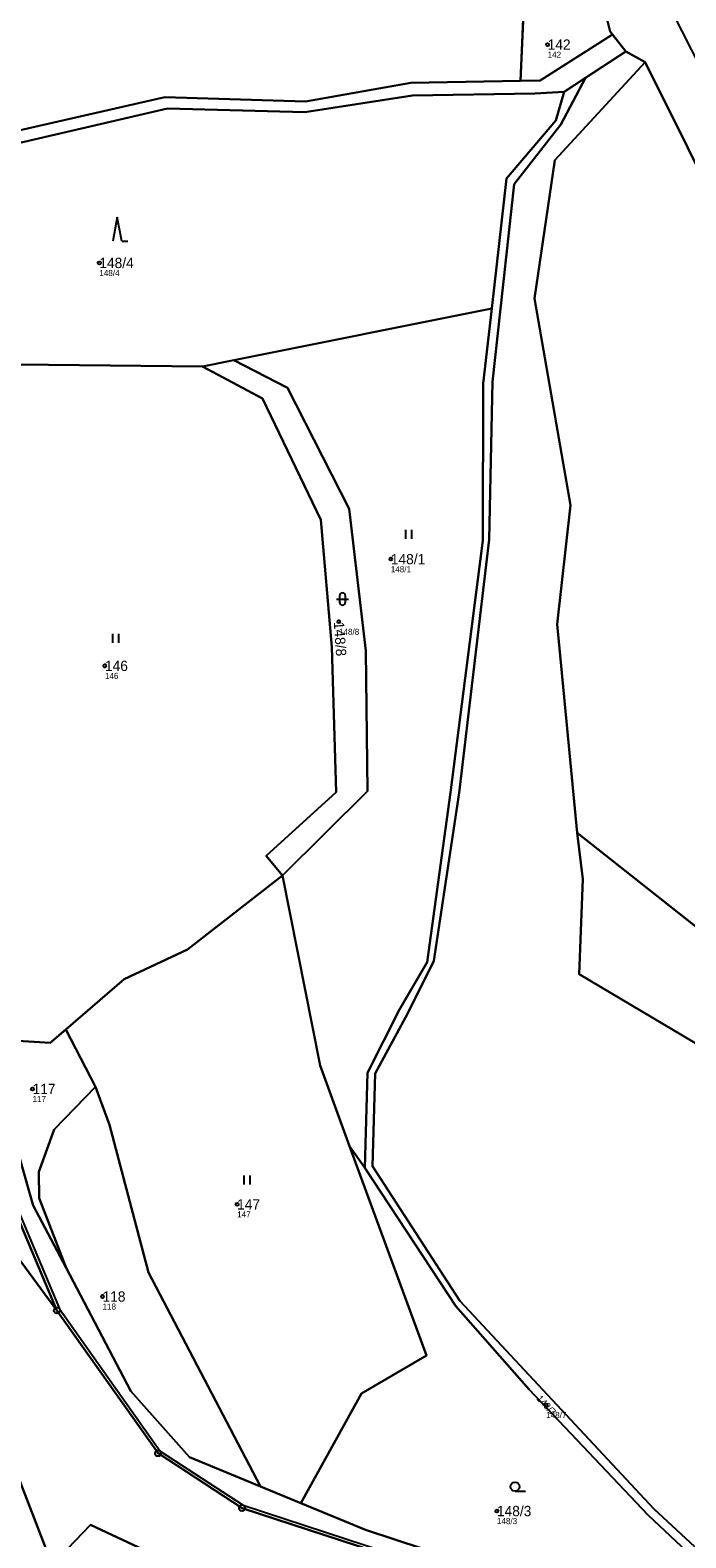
# Model space of a CAD drawing. Extents: x -770088 to -765625, y -1057899 to -1053934.
# Drawn here: x -768095.1 to -767987, y -1054686.7 to -1054438.1 of the extents above; entities that cross this region are included whole.
import ezdxf

# ---------------------------------------------------------------- set-up
doc = ezdxf.new("R2010")
doc.units = 0
for name, color, linetype in [('Definiční body', 7, 'Continuous'), ('Hranice parcel', 7, 'Continuous'), ('Parcelní čísla', 7, 'Continuous'), ('Polygon parcely', 7, 'Continuous'), ('Poz předměty', 7, 'Continuous'), ('Vnitřní kresba', 7, 'Continuous'), ('Značky bodu BP', 7, 'Continuous'), ('Značky kultur', 7, 'Continuous')]:
    doc.layers.add(name, color=color, linetype=linetype)

msp = doc.modelspace()

# ---------------------------------------------------------------- linework, layer by layer
at = {"layer": 'Definiční body'}
for centre in [(-768009.84, -1054440.53), (-768083.75, -1054476.52), (-768035.69, -1054525.35), (-768044.24, -1054535.67), (-768082.82, -1054542.94), (-768094.76, -1054612.7), (-768061.03, -1054631.72), (-768083.22, -1054646.91), (-768010.07, -1054664.79), (-768018.2, -1054682.28)]:
    msp.add_circle(centre, 0.25, dxfattribs=at)
at = {"layer": 'Hranice parcel'}
for p, q in [((-768014.32, -1054446.48), (-768012.63, -1054409.53)), ((-768011.07, -1054446.42), (-767999.13, -1054438.86)), ((-767996.92, -1054441.64), (-767999.13, -1054438.86)), ((-767996.92, -1054441.64), (-768003.58, -1054446.01)), ((-767993.75, -1054443.41), (-767996.92, -1054441.64)), ((-768003.58, -1054446.01), (-768007.65, -1054453.72)), ((-768003.58, -1054446.01), (-768007.12, -1054448.33)), ((-768014.32, -1054446.48), (-768011.07, -1054446.42)), ((-768019.05, -1054484.05), (-768016.59, -1054462.59)), ((-768019.05, -1054484.05), (-768061.59, -1054492.55)), ((-768020.47, -1054496.39), (-768019.05, -1054484.05)), ((-768066.71, -1054493.58), (-768061.59, -1054492.55)), ((-768004.98, -1054570.49), (-767952.69, -1054611.77)), ((-768089.29, -1054602.92), (-768084.35, -1054612.32)), ((-768042.48, -1054622.1), (-768039.98, -1054625.68)), ((-768068.87, -1054673.41), (-768057.15, -1054678.25)), ((-768057.15, -1054678.25), (-768050.53, -1054680.98)), ((-768050.53, -1054680.98), (-768039.86, -1054685.38))]:
    msp.add_line(p, q, dxfattribs=at)
for points in [[(-767999.13, -1054438.86), (-767999.51, -1054438.37), (-768000.9, -1054433), (-768001.9, -1054430.25)], [(-768004.98, -1054570.49), (-768008.26, -1054536.06), (-768006.08, -1054516.43), (-768011.97, -1054482.37), (-768008.62, -1054459.57), (-767993.75, -1054443.41)], [(-767932.49, -1054594.98), (-767947.43, -1054549.64), (-767965.69, -1054499.79), (-767993.75, -1054443.41)], [(-768129.66, -1054522.44), (-768143.72, -1054508.36), (-768153.51, -1054496.13), (-768145.69, -1054479.12), (-768128.76, -1054467.46), (-768108.88, -1054457.38), (-768072.94, -1054449.18), (-768049.77, -1054449.9), (-768032.41, -1054446.8), (-768014.32, -1054446.48)], [(-768007.12, -1054448.33), (-768011.94, -1054448.56), (-768032.09, -1054448.91), (-768049.87, -1054451.68), (-768072.5, -1054451.08), (-768107.99, -1054459.29), (-768127.24, -1054469.4), (-768144.62, -1054481.32), (-768150.8, -1054495.47), (-768142.12, -1054506.4), (-768138.56, -1054510)], [(-768016.59, -1054462.59), (-768008.46, -1054453.04), (-768007.12, -1054448.33)], [(-768007.65, -1054453.72), (-768015.36, -1054463.55), (-768018.91, -1054496.12), (-768019.46, -1054522.13), (-768024.43, -1054563.88), (-768028.6, -1054591.56), (-768032.87, -1054600.19), (-768038.24, -1054610.16), (-768038.7, -1054625.42), (-768024.3, -1054647.61), (-767992.32, -1054681.94), (-767984.09, -1054689.56)], [(-768066.71, -1054493.58), (-768097.17, -1054493.26), (-768124.91, -1054502.9)], [(-768061.59, -1054492.55), (-768052.73, -1054497.13), (-768042.56, -1054517.08), (-768039.81, -1054540.47), (-768039.55, -1054563.6), (-768053.52, -1054577.48)], [(-768053.52, -1054577.48), (-768056.26, -1054574.26), (-768044.72, -1054563.77), (-768045.4, -1054539.87), (-768047.21, -1054518.89), (-768056.86, -1054498.85), (-768066.71, -1054493.58)], [(-768039.98, -1054625.68), (-768039.52, -1054610.02), (-768034.26, -1054599.61), (-768029.7, -1054591.8), (-768025.82, -1054563.82), (-768020.53, -1054522.28), (-768020.47, -1054496.39)], [(-767952.69, -1054611.77), (-767961.76, -1054619.22), (-768004.62, -1054593.77), (-768004.01, -1054578.13), (-768004.98, -1054570.49)], [(-768089.29, -1054602.92), (-768079.66, -1054594.62), (-768069.23, -1054589.69), (-768053.52, -1054577.48)], [(-768042.48, -1054622.1), (-768047.34, -1054608.85), (-768053.52, -1054577.48)], [(-768103.45, -1054604.38), (-768091.83, -1054605.1), (-768089.29, -1054602.92)], [(-768090.72, -1054649.21), (-768097.97, -1054632.05), (-768103.4, -1054615), (-768106.26, -1054607.33)], [(-768084.35, -1054612.32), (-768091.18, -1054619.39), (-768093.74, -1054626.36), (-768093.67, -1054630.71), (-768089.23, -1054642.19)], [(-768057.15, -1054678.25), (-768075.64, -1054642.95), (-768082.06, -1054618.63), (-768084.35, -1054612.32)], [(-768089.23, -1054642.19), (-768094.64, -1054631.93), (-768098.83, -1054617.23)], [(-768114.36, -1054622.39), (-768110.66, -1054620.35), (-768106.49, -1054627.9), (-768090.72, -1054649.21)], [(-768091.51, -1054691.14), (-768104.48, -1054657.68), (-768112.02, -1054633.85), (-768114.36, -1054622.39)], [(-768050.53, -1054680.98), (-768040.54, -1054662.9), (-768029.82, -1054656.63), (-768042.48, -1054622.1)], [(-767931.74, -1054768.14), (-767931.44, -1054758.8), (-767936.62, -1054749.49), (-767951.16, -1054722.75), (-767974.99, -1054700.13), (-767993.27, -1054682.98), (-768012.87, -1054662.27), (-768024.96, -1054648.49), (-768039.98, -1054625.68)], [(-768089.23, -1054642.19), (-768078.52, -1054662.51), (-768068.87, -1054673.41)], [(-767968, -1054727.23), (-768001.95, -1054702.62), (-768016.95, -1054695.94), (-768060.2, -1054681.78), (-768074.06, -1054672.76), (-768090.72, -1054649.21)], [(-768091.51, -1054691.14), (-768085.17, -1054684.55), (-768066.76, -1054693.17), (-768053.98, -1054697.96), (-768050.09, -1054703.07), (-768035.06, -1054714.6), (-768021.61, -1054726.81), (-768017.92, -1054728.84), (-768013.91, -1054731.45), (-767995.48, -1054757.12)], [(-768039.86, -1054685.38), (-768011.31, -1054694.75), (-768001.18, -1054699.79), (-767994.33, -1054704.31), (-767972.32, -1054720.42), (-767961.3, -1054728.83), (-767941.91, -1054747.99), (-767934.66, -1054760.27), (-767931.74, -1054768.14)]]:
    msp.add_lwpolyline(points, dxfattribs=at)
at = {"layer": 'Polygon parcely'}
for points in [[(-768108.88, -1054457.38), (-768072.94, -1054449.18), (-768049.77, -1054449.9), (-768032.41, -1054446.8), (-768014.32, -1054446.48), (-768012.63, -1054409.53)], [(-768000.9, -1054433), (-767999.51, -1054438.37), (-767999.13, -1054438.86), (-767996.92, -1054441.64), (-767993.75, -1054443.41), (-767965.69, -1054499.79), (-767947.43, -1054549.64), (-767932.49, -1054594.98), (-767914.06, -1054628.49), (-767911.41, -1054626.68), (-767903.01, -1054638.57), (-767897.05, -1054647), (-767882.98, -1054666.9), (-767874.18, -1054679.35), (-767864.97, -1054691.97), (-767847.09, -1054711.31), (-767838.93, -1054720.15), (-767832.46, -1054727.15), (-767814.04, -1054742.81), (-767801.61, -1054749.28), (-767725.45, -1054824.62), (-767692.81, -1054850)], [(-768107.99, -1054459.29), (-768072.5, -1054451.08), (-768049.87, -1054451.68), (-768032.09, -1054448.91), (-768011.94, -1054448.56), (-768007.12, -1054448.33), (-768003.58, -1054446.01), (-767996.92, -1054441.64), (-767999.13, -1054438.86), (-768011.07, -1054446.42), (-768014.32, -1054446.48), (-768032.41, -1054446.8), (-768049.77, -1054449.9), (-768072.94, -1054449.18), (-768108.88, -1054457.38)], [(-767961.76, -1054619.22), (-768004.62, -1054593.77), (-768004.01, -1054578.13), (-768004.98, -1054570.49), (-768008.26, -1054536.06), (-768006.08, -1054516.43), (-768011.97, -1054482.37), (-768008.62, -1054459.57), (-767993.75, -1054443.41), (-767996.92, -1054441.64), (-768003.58, -1054446.01), (-768007.65, -1054453.72), (-768015.36, -1054463.55), (-768018.91, -1054496.12), (-768019.46, -1054522.13), (-768024.43, -1054563.88), (-768028.6, -1054591.56), (-768032.87, -1054600.19), (-768038.24, -1054610.16), (-768038.7, -1054625.42), (-768024.3, -1054647.61), (-767992.32, -1054681.94), (-767984.09, -1054689.56)], [(-767984.09, -1054689.56), (-767992.32, -1054681.94), (-768024.3, -1054647.61), (-768038.7, -1054625.42), (-768038.24, -1054610.16), (-768032.87, -1054600.19), (-768028.6, -1054591.56), (-768024.43, -1054563.88), (-768019.46, -1054522.13), (-768018.91, -1054496.12), (-768015.36, -1054463.55), (-768007.65, -1054453.72), (-768003.58, -1054446.01), (-768007.12, -1054448.33), (-768008.46, -1054453.04), (-768016.59, -1054462.59), (-768019.05, -1054484.05), (-768020.47, -1054496.39), (-768020.53, -1054522.28), (-768025.82, -1054563.82), (-768029.7, -1054591.8), (-768034.26, -1054599.61), (-768039.52, -1054610.02), (-768039.98, -1054625.68), (-768024.96, -1054648.49), (-768012.87, -1054662.27), (-767993.27, -1054682.98), (-767974.99, -1054700.13)], [(-768011.31, -1054694.75), (-768039.86, -1054685.38), (-768050.53, -1054680.98), (-768057.15, -1054678.25), (-768068.87, -1054673.41), (-768078.52, -1054662.51), (-768089.23, -1054642.19), (-768094.64, -1054631.93), (-768098.83, -1054617.23)], [(-768097.97, -1054632.05), (-768090.72, -1054649.21), (-768074.06, -1054672.76), (-768060.2, -1054681.78), (-768016.95, -1054695.94)]]:
    msp.add_lwpolyline(points, dxfattribs=at)
for points in [[(-768011.07, -1054446.42), (-767999.13, -1054438.86), (-767999.51, -1054438.37), (-768000.9, -1054433), (-768001.9, -1054430.25), (-768008.13, -1054434.58), (-768010.27, -1054412.89), (-768012.63, -1054409.53), (-768014.32, -1054446.48)], [(-767993.75, -1054443.41), (-768008.62, -1054459.57), (-768011.97, -1054482.37), (-768006.08, -1054516.43), (-768008.26, -1054536.06), (-768004.98, -1054570.49), (-767952.69, -1054611.77), (-767946.58, -1054606.74), (-767932.49, -1054594.98), (-767947.43, -1054549.64), (-767965.69, -1054499.79)], [(-768019.05, -1054484.05), (-768016.59, -1054462.59), (-768008.46, -1054453.04), (-768007.12, -1054448.33), (-768011.94, -1054448.56), (-768032.09, -1054448.91), (-768049.87, -1054451.68), (-768072.5, -1054451.08), (-768107.99, -1054459.29), (-768127.24, -1054469.4), (-768144.62, -1054481.32), (-768150.8, -1054495.47), (-768142.12, -1054506.4), (-768138.56, -1054510), (-768124.91, -1054502.9), (-768097.17, -1054493.26), (-768066.71, -1054493.58), (-768061.59, -1054492.55)], [(-768025.82, -1054563.82), (-768020.53, -1054522.28), (-768020.47, -1054496.39), (-768019.05, -1054484.05), (-768061.59, -1054492.55), (-768052.73, -1054497.13), (-768042.56, -1054517.08), (-768039.81, -1054540.47), (-768039.55, -1054563.6), (-768053.52, -1054577.48), (-768047.34, -1054608.85), (-768042.48, -1054622.1), (-768039.98, -1054625.68), (-768039.52, -1054610.02), (-768034.26, -1054599.61), (-768029.7, -1054591.8)], [(-768069.23, -1054589.69), (-768053.52, -1054577.48), (-768056.26, -1054574.26), (-768044.72, -1054563.77), (-768045.4, -1054539.87), (-768047.21, -1054518.89), (-768056.86, -1054498.85), (-768066.71, -1054493.58), (-768097.17, -1054493.26), (-768124.91, -1054502.9), (-768115.73, -1054532.85), (-768105.46, -1054598.9), (-768103.45, -1054604.38), (-768091.83, -1054605.1), (-768089.29, -1054602.92), (-768079.66, -1054594.62)], [(-768053.52, -1054577.48), (-768039.55, -1054563.6), (-768039.81, -1054540.47), (-768042.56, -1054517.08), (-768052.73, -1054497.13), (-768061.59, -1054492.55), (-768066.71, -1054493.58), (-768056.86, -1054498.85), (-768047.21, -1054518.89), (-768045.4, -1054539.87), (-768044.72, -1054563.77), (-768056.26, -1054574.26)], [(-767952.69, -1054611.77), (-768004.98, -1054570.49), (-768004.01, -1054578.13), (-768004.62, -1054593.77), (-767961.76, -1054619.22)], [(-768089.29, -1054602.92), (-768084.35, -1054612.32), (-768082.06, -1054618.63), (-768075.64, -1054642.95), (-768057.15, -1054678.25), (-768050.53, -1054680.98), (-768040.54, -1054662.9), (-768029.82, -1054656.63), (-768042.48, -1054622.1), (-768047.34, -1054608.85), (-768053.52, -1054577.48), (-768069.23, -1054589.69), (-768079.66, -1054594.62)], [(-768107.8, -1054607.68), (-768117.43, -1054591.21), (-768124.72, -1054593.33), (-768123.55, -1054596.45), (-768114.36, -1054622.39), (-768110.66, -1054620.35), (-768106.49, -1054627.9), (-768090.72, -1054649.21), (-768097.97, -1054632.05), (-768103.4, -1054615), (-768106.26, -1054607.33)], [(-768135.13, -1054684.39), (-768135.76, -1054687.61), (-768131.99, -1054691.07), (-768121.57, -1054697.67), (-768094.16, -1054712.91), (-768059.31, -1054736.14), (-768073.76, -1054717.03), (-768091.51, -1054691.14), (-768104.48, -1054657.68), (-768112.02, -1054633.85), (-768114.36, -1054622.39), (-768123.55, -1054596.45), (-768124.72, -1054593.33), (-768164.23, -1054611.92), (-768142.11, -1054670.64)], [(-768089.23, -1054642.19), (-768093.67, -1054630.71), (-768093.74, -1054626.36), (-768091.18, -1054619.39), (-768084.35, -1054612.32), (-768089.29, -1054602.92), (-768091.83, -1054605.1), (-768103.45, -1054604.38), (-768098.83, -1054617.23), (-768094.64, -1054631.93)], [(-768082.06, -1054618.63), (-768084.35, -1054612.32), (-768091.18, -1054619.39), (-768093.74, -1054626.36), (-768093.67, -1054630.71), (-768089.23, -1054642.19), (-768078.52, -1054662.51), (-768068.87, -1054673.41), (-768057.15, -1054678.25), (-768075.64, -1054642.95)], [(-768016.95, -1054695.94), (-768060.2, -1054681.78), (-768074.06, -1054672.76), (-768090.72, -1054649.21), (-768106.49, -1054627.9), (-768110.66, -1054620.35), (-768114.36, -1054622.39), (-768112.02, -1054633.85), (-768104.48, -1054657.68), (-768091.51, -1054691.14), (-768085.17, -1054684.55), (-768066.76, -1054693.17), (-768053.98, -1054697.96), (-768050.09, -1054703.07), (-768035.06, -1054714.6), (-768021.61, -1054726.81), (-768017.92, -1054728.84), (-768013.91, -1054731.45), (-767995.48, -1054757.12), (-767968, -1054727.23), (-768001.95, -1054702.62)], [(-768050.53, -1054680.98), (-768039.86, -1054685.38), (-768011.31, -1054694.75), (-768001.18, -1054699.79), (-767994.33, -1054704.31), (-767972.32, -1054720.42), (-767961.3, -1054728.83), (-767941.91, -1054747.99), (-767934.66, -1054760.27), (-767931.74, -1054768.14), (-767931.44, -1054758.8), (-767936.62, -1054749.49), (-767951.16, -1054722.75), (-767974.99, -1054700.13), (-767993.27, -1054682.98), (-768012.87, -1054662.27), (-768024.96, -1054648.49), (-768039.98, -1054625.68), (-768042.48, -1054622.1), (-768029.82, -1054656.63), (-768040.54, -1054662.9)], [(-767988.53, -1054777.11), (-767988.56, -1054770.25), (-767996.82, -1054761.35), (-767995.48, -1054757.12), (-768013.91, -1054731.45), (-768017.92, -1054728.84), (-768021.61, -1054726.81), (-768035.06, -1054714.6), (-768050.09, -1054703.07), (-768053.98, -1054697.96), (-768066.76, -1054693.17), (-768085.17, -1054684.55), (-768091.51, -1054691.14), (-768073.76, -1054717.03), (-768059.31, -1054736.14), (-768015.12, -1054767.69), (-767990.6, -1054785.57)]]:
    msp.add_lwpolyline(points, close=True, dxfattribs=at)
at = {"layer": 'Poz předměty'}
msp.add_line((-767982.99, -1054447.49), (-767989.19, -1054435.27), dxfattribs=at)
at = {"layer": 'Vnitřní kresba'}
for p, q in [((-768097.52, -1054631.81), (-768090.29, -1054648.94)), ((-768090.29, -1054648.94), (-768073.7, -1054672.4)), ((-768073.7, -1054672.4), (-768060, -1054681.31)), ((-768060, -1054681.31), (-768016.77, -1054695.47))]:
    msp.add_line(p, q, dxfattribs=at)
at = {"layer": 'Značky bodu BP'}
for centre, radius in [((-768090.72, -1054649.21), 0.5), ((-768090.72, -1054649.21), 0.0303), ((-768074.06, -1054672.76), 0.5), ((-768074.06, -1054672.76), 0.0303), ((-768060.2, -1054681.78), 0.5), ((-768060.2, -1054681.78), 0.0303)]:
    msp.add_circle(centre, radius, dxfattribs=at)
at = {"layer": 'Značky kultur'}
for p, q in [((-768080.79, -1054468.95), (-768081.54, -1054472.95)), ((-768080.04, -1054472.95), (-768080.79, -1054468.95)), ((-768080.04, -1054472.95), (-768079.04, -1054472.95)), ((-768033.23, -1054522.01), (-768033.23, -1054520.51)), ((-768032.23, -1054522.01), (-768032.23, -1054520.51)), ((-768044.65, -1054531.93), (-768042.65, -1054531.93)), ((-768044.15, -1054531.43), (-768044.15, -1054532.43)), ((-768043.15, -1054532.43), (-768043.15, -1054531.43)), ((-768081.53, -1054539.17), (-768081.53, -1054537.67)), ((-768080.53, -1054539.17), (-768080.53, -1054537.67)), ((-768059.86, -1054628.46), (-768059.86, -1054626.96)), ((-768058.86, -1054628.46), (-768058.86, -1054626.96)), ((-768015.21, -1054679.02), (-768013.46, -1054679.02))]:
    msp.add_line(p, q, dxfattribs=at)
msp.add_circle((-768015.21, -1054678.27), 0.75, dxfattribs=at)
for centre, start, end in [((-768043.65, -1054531.43), 0, 180), ((-768043.65, -1054532.43), 180, 359.9879)]:
    msp.add_arc(centre, 0.5, start, end, dxfattribs=at)

# ---------------------------------------------------------------- texts
at = {"layer": 'Definiční body'}
for s, p in [('142', (-768009.84, -1054442.69)), ('148/4', (-768083.75, -1054478.68)), ('148/1', (-768035.69, -1054527.51)), ('148/8', (-768044.24, -1054537.83)), ('146', (-768082.82, -1054545.1)), ('117', (-768094.76, -1054614.86)), ('147', (-768061.03, -1054633.88)), ('118', (-768083.22, -1054649.07)), ('148/7', (-768010.07, -1054666.95)), ('148/3', (-768018.2, -1054684.44))]:
    msp.add_text(s, height=1, dxfattribs=at).set_placement(p)
at = {"layer": 'Parcelní čísla'}
for s, p in [('142', (-768009.84, -1054441.38)), ('148/4', (-768083.75, -1054477.37)), ('148/1', (-768035.69, -1054526.2)), ('146', (-768082.82, -1054543.79)), ('117', (-768094.76, -1054613.55)), ('147', (-768061.03, -1054632.57)), ('118', (-768083.22, -1054647.76)), ('148/3', (-768018.2, -1054683.13))]:
    msp.add_text(s, height=1.7, dxfattribs=at).set_placement(p)
for s, height, rotation, p in [('148/8', 1.7, 274, (-768045.09, -1054535.73)), ('148/7', 1.14, 313, (-768011.76, -1054663.82))]:
    msp.add_text(s, height=height, rotation=rotation, dxfattribs=at).set_placement(p)

doc.saveas('drawing.dxf')
